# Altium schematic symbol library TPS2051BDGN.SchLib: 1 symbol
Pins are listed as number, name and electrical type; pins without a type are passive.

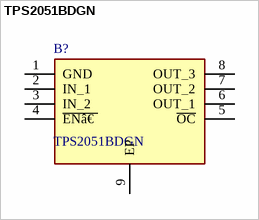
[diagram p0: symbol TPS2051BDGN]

## TPS2051BDGN
designator B?
Single, Current-Limited, Power-Distribution Switch; Manufacturer_Name: Texas Instruments; Geometry.Height: 1.1mm
footprint SOP65P490X110-9N
pins: 1 GND, 2 IN_1, 3 IN_2, 4 ~{ENâ€ }, 5 ~{OC}, 6 OUT_1, 7 OUT_2, 8 OUT_3, 9 EP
